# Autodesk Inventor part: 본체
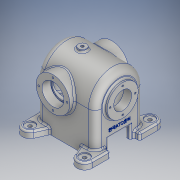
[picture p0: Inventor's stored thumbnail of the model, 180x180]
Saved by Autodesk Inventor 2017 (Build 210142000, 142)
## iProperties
Part Number: 본체
Material: 알루미늄 6061
Document SubType Name: Modeling
Designer: MRC
Density: 2.7 g/cm^3
Appearance: 알루미늄 - 평지
Mass: 1388.29 g
Surface Area: 1150.5 cm^2
Volume: 514.181 cm^3
Author: MRC
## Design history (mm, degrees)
sketch "스케치3"
  geometry: L1 (45, 0)-(45, -76); L2 (45, -76)-(-45, -76); L3 (-45, -76)-(-45, 0); A1 r 45 centre (0, 0) between (45, 0) and (-45, 0); 1 further point
  constraints: 6 end point, 2 point on circle, 1 centre point, 1 coincident, 1 parallel, 1 perpendicular, 1 tangent, 1 vertical
  dimensions: "d6" = 90 diameter of A1; "d13" = 76 distance of L1.start L1.end; "d14" = 76 distance of L2.end L3.end
extrude "돌출2" new body sketch "스케치3" stored distance "d15" = 108; taper "d16" = 0 deg
sketch "스케치5"
  geometry: C1 r 28.5 at (0, 0); 1 further point
  constraints: 1 centre point, 1 coincident
  dimensions: "d23" = 57 diameter of C1
extrude "돌출3" join sketch "스케치5" distance "d24" = 6; taper "d25" = 0 deg
sketch "스케치7"
  geometry: L1 (28.5, 60)-(-28.5, 60) reference; L2 (0, 60)-(0, -14); L3 (0, -54)-(0, 54) reference; C1 r 31 at (0, -14); 1 further point
  constraints: 2 end point, 1 centre point, 1 coincident, 1 midpoint, 1 point on line
  dimensions: "d29" = 74 distance of L2.start L2.end; "d30" = 62 diameter of C1
extrude "돌출5" join sketch "스케치7" stored distance "d31" = 108; taper "d32" = 0 deg
sketch "스케치8"
  geometry: L1 (0, -14)-(49, -14); C1 r 31 at (0, -14) reference; 1 further point
  constraints: 2 end point, 1 horizontal
  dimensions: "d33" = 49 distance of L1.start L1.end
node "작업 평면1"
sketch "스케치9"
  geometry: C1 r 7.5 at (0, 0); 2 further points
  constraints: 1 centre point, 1 coincident
  dimensions: "d35" = 15 diameter of C1
extrude "돌출6" join sketch "스케치9" distance "d36" = 28; taper "d37" = 0 deg
node "작업 평면2"
sketch "스케치11"
  geometry: L1 (45, 0)-(-45, 0); A1 r 45 centre (0, 0) between (45, 0) and (-45, 0) reference; A2 r 45 centre (0, 0) between (45, 0) and (-45, 0) reference; A3 r 45 centre (0, 0) between (-45, 0) and (45, 0); 1 further point
  constraints: 2 end point, 2 point on circle, 1 centre point, 1 coincident, 1 horizontal
sketch "스케치14"
  geometry: L1 (-45, -76)-(-45, 0) reference; L2 (45, 0)-(45, -76) reference; L3 (-36, -76)-(-36, -27); L4 (36, -27)-(36, -76); L5 (-36, -76)-(36, -76); L6 (45, -76)-(-45, -76) reference; A1 r 45 centre (0, 0) between (-45, 0) and (45, 0) reference; 1 further point
  constraints: 6 end point, 2 parallel, 2 point on circle, 1 collinear
  dimensions: "d57" = 9 distance between parallel lines of L1 L3; "d58" = 9 distance between parallel lines of L2 L4
extrude "돌출9" cut sketch "스케치14" stored distance "d59" = 90; taper "d60" = 0 deg
sketch "스케치15"
  geometry: C1 r 17.5 at (0, 0); C2 r 31 at (0, 0) reference
  constraints: 1 centre point, 1 coincident
  dimensions: "d62" = 35 diameter of C1
extrude "돌출10" cut sketch "스케치15" distance "d63" = 146; taper "d64" = 0 deg
sketch "스케치16"
  geometry: C1 r 20 at (0, 0); C2 r 17.5 at (0, 0) reference; 1 further point
  constraints: 1 centre point, 1 coincident
  dimensions: "d65" = 40 diameter of C1
extrude "돌출11" cut sketch "스케치16" distance "d66" = 16; taper "d67" = 0 deg
sketch "스케치17"
  geometry: C1 r 16.5 at (0, 0); 1 further point
  constraints: 1 centre point, 1 coincident
  dimensions: "d68" = 33 diameter of C1
extrude "돌출12" cut sketch "스케치17" distance "d69" = 101.5; taper "d70" = 0 deg
sketch "스케치18"
  geometry: L1 (0, -45)-(0, -54) reference; L2 (0, -54)-(0, -45); L3 (0, -45)-(36, -45); L4 (36, -45)-(36, 45); L5 (36, 45)-(0, 45); L6 (0, 54)-(0, 17) reference; L7 (45, 54)-(0, 54) reference; L8 (0, -54)-(45, -54) reference; L9 (-16.5, 60)-(16.5, 60) reference; L10 (0, -45)-(0, 45); L11 (0, 45)-(0, 60); 1 further point
  constraints: 12 end point, 7 perpendicular, 3 vertical, 1 midpoint, 1 point on line
  dimensions: "d73" = 72 diameter of L4 L2; "d77" = 9 distance between parallel lines of L5 L7; "d78" = 9 distance between parallel lines of L8 L3
revolve "회전2" sketch "스케치18" stored, may be unused: angle "d80" = 90 deg
sketch "스케치19"
  geometry: L1 (9, -99)-(9, -9) reference; L2 (9, -99)-(81, -99) reference; L3 (81, -9)-(81, -99) reference; L4 (81, -9)-(9, -9) reference; L5 (0, -108)-(0, 0) reference; L6 (90, -108)-(0, -108) reference; L7 (-20.693, -91.21)-(0, -82); L8 (0, -108)-(0, -99) reference; L9 (0, -82)-(0, -108); L10 (0, -108)-(18, -108); L11 (0, -108)-(90, -108) reference; L12 (18, -108)-(18, -118); L13 (18, -118)-(-15, -118); A1 r 14 centre (-15, -104) between (-20.693, -91.21) and (-15, -118); 1 further point
  constraints: 10 end point, 2 point on circle, 2 point on line, 2 tangent, 1 centre point, 1 collinear, 1 vertical
  dimensions: "d81" = 60 horizontal distance of point (45, -54) A1.centre; "d82" = 50 vertical distance of point (45, -54) A1.centre; "d83" = 28 diameter of A1; "d85" = 18 distance between parallel lines of L5 L12; "d86" = 33 distance of L12.end L13.end; "d87" = 20.69259 horizontal distance of L7.start L7.end
extrude "돌출13" join sketch "스케치19" distance "d88" = 12; taper "d89" = 0 deg
sketch "스케치20"
  geometry: A1 r 14 centre (-15, 104) between (-15, 118) and (-20.693, 91.21) reference; 2 further points
  constraints: 1 coincident
hole "구멍1" sketch "스케치20" at (-15, 104) diameter "d90" = 6.6; stored, may be unused: countersink angle "d94" = 90 deg, drill point angle "d96" = 0 deg; dims "d91" = 6, "d92" = 18, "d93" = 2, "d95" = 12
sketch "스케치22"
  geometry: A1 r 26 centre (0, 0) between (0, 26) and (26, 0); 3 further points
  constraints: 4 point on circle, 2 horizontal alignment, 2 vertical alignment, 1 centre point, 1 coincident
  dimensions: "d100" = 52 diameter of A1
hole "구멍2" sketch "스케치22" at (0, 26), (26, 0), (0, -26), (-26, 0) diameter "d101" = 3.242; stored, may be unused: countersink angle "d105" = 90 deg, drill point angle "d107" = 118 deg; dims "d102" = 8, "d103" = 19.05, "d104" = 4.775, "d106" = 10
sketch "스케치23"
  geometry: A1 r 23 centre (0, 0) between (0, 23) and (23, 0); 3 further points
  constraints: 4 point on circle, 2 horizontal alignment, 2 vertical alignment, 1 centre point, 1 coincident
  dimensions: "d108" = 46 diameter of A1
hole "구멍3" sketch "스케치23" at (0, 23), (23, 0), (-23, 0), (0, -23) diameter "d109" = 3.242; stored, may be unused: countersink angle "d113" = 90 deg, drill point angle "d115" = 118 deg; dims "d110" = 8, "d111" = 19.05, "d112" = 4.775, "d114" = 10
sketch "스케치24"
  geometry: 2 further points
  constraints: 1 other
hole "구멍4" sketch "스케치24" at (0, 0) diameter "d116" = 5.188; stored, may be unused: countersink angle "d120" = 90 deg, drill point angle "d122" = 118 deg; dims "d117" = 16, "d118" = 19.05, "d119" = 4.775, "d121" = 16
fillet "모깎기1" dims "d123" = 0.3
fillet "모깎기2" dims "d124" = 3
fillet "모깎기4" dims "d126" = 3
sketch "스케치25"
  geometry: L1 (-36, -76)-(36, -76) reference; L2 (-20, -76)-(20, -76); L3 (20, -76)-(20, -53); L4 (20, -53)-(-20, -53); L5 (-20, -53)-(-20, -76); 1 further point
  constraints: 8 end point, 2 parallel, 1 horizontal, 1 perpendicular, 1 point on line
  dimensions: "d127" = 20 distance from line of point (0, 0) L5; "d128" = 40 distance of L3.end L4.end; "d129" = 23 distance between parallel lines of L1 L4
extrude "돌출14" cut sketch "스케치25" stored distance "d130" = 156.75; taper "d131" = 0 deg
fillet "모깎기5" dims "d132" = 3
fillet "모깎기6" dims "d133" = 3
fillet "모깎기7" dims "d134" = 3
fillet "모깎기8" dims "d135" = 3
fillet "모깎기9" dims "d136" = 12
fillet "모깎기10" dims "d137" = 3
sketch "스케치26"
  geometry: L1 (60, -76)-(30, -76) reference; 2 further points
  constraints: 1 vertical alignment, 1 other
  dimensions: "d138" = 35 distance from line of L1 point (0, -41)
feature "엠보싱1" sketch "스케치26" dims "d139" = 0.5, "d140" = 0
sketch "스케치27"
  geometry: L1 (49, -6.5)-(49, -21.5) reference; L2 (49, -14)-(-49, -14); 1 further point
  constraints: 2 end point, 1 horizontal, 1 midpoint
  dimensions: "d141" = 98 distance of L2.start L2.end
node "작업 평면3"
sketch "스케치29"
  geometry: C1 r 7.5 at (0, 0) reference; C2 r 2.594 at (0, 0) reference; C3 r 7.5 at (0, 0); C4 r 2.594 at (0, 0); 1 further point
  constraints: 2 centre point, 2 coincident, 2 concentric
extrude "돌출16" join sketch "스케치29" stored distance "d146" = 10; taper "d147" = 0 deg
sketch "스케치30"
  geometry: 2 further points
  constraints: 1 other
hole "구멍5" sketch "스케치30" at (0, 0) diameter "d148" = 5.188; stored, may be unused: countersink angle "d152" = 90 deg, drill point angle "d154" = 118 deg; dims "d149" = 16, "d150" = 4, "d151" = 2, "d153" = 16
fillet "모깎기12" dims "d155" = 3
node "솔리드2"
mirror "미러1"
mirror "미러2"
mirror "미러3"
node "투영된 루프1"
other parameters: "d43" = -12
